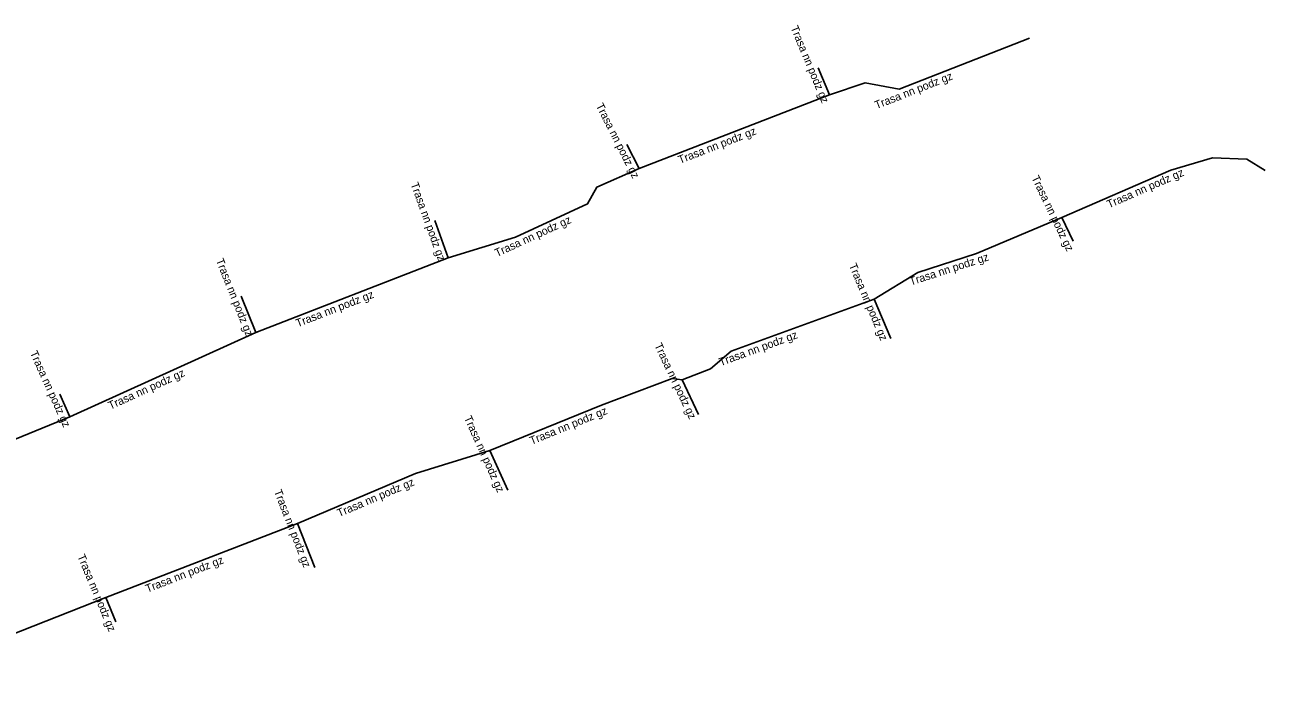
# Model space of a CAD drawing. Extents: x -467803 to -467116, y -1117596 to -1116713.
# Drawn here: x -467305.8 to -467228.3, y -1117118.8 to -1117076.7 of the extents above; entities that cross this region are included whole.
import ezdxf

# ---------------------------------------------------------------- set-up
doc = ezdxf.new("R2010")
doc.units = 0
doc.layers.add('Popiskový text - Ostatní atributy Trasy', color=7, linetype='Continuous')
doc.layers.add('Spojnice NN', color=7, linetype='Continuous')

msp = doc.modelspace()

# ---------------------------------------------------------------- linework, layer by layer
at = {"layer": 'Spojnice NN'}
for points in [[(-467255.53, -1117081.06), (-467253.29, -1117080.32), (-467251.17, -1117080.71), (-467243.03, -1117077.52)], [(-467255.53, -1117081.06), (-467256.23, -1117079.37)], [(-467267.43, -1117085.68), (-467255.53, -1117081.06)], [(-467267.43, -1117085.68), (-467268.19, -1117084.17)], [(-467228.297, -1117085.804), (-467229.435, -1117085.098), (-467231.59, -1117085.01), (-467234.2, -1117085.77), (-467241, -1117088.74)], [(-467279.36, -1117091.25), (-467275.15, -1117089.96), (-467270.65, -1117087.89), (-467270.07, -1117086.84), (-467267.43, -1117085.68)], [(-467279.36, -1117091.25), (-467280.2, -1117088.92)], [(-467241, -1117088.74), (-467246.34, -1117090.98), (-467250.01, -1117092.17), (-467252.73, -1117093.84)], [(-467241, -1117088.74), (-467240.29, -1117090.22)], [(-467291.39, -1117095.92), (-467279.36, -1117091.25)], [(-467291.39, -1117095.92), (-467292.29, -1117093.66)], [(-467252.73, -1117093.84), (-467261.67, -1117097.1), (-467262.96, -1117098.2), (-467264.74, -1117098.89)], [(-467252.73, -1117093.84), (-467251.7, -1117096.29)], [(-467303, -1117101.19), (-467291.39, -1117095.92)], [(-467264.74, -1117098.89), (-467265.37, -1117098.81), (-467269.77, -1117100.46), (-467276.75, -1117103.31)], [(-467264.74, -1117098.89), (-467263.72, -1117101.05)], [(-467303, -1117101.19), (-467303.64, -1117099.77)], [(-467314.67, -1117105.96), (-467303, -1117101.19)], [(-467276.75, -1117103.31), (-467281.4, -1117104.74), (-467288.77, -1117107.87)], [(-467276.75, -1117103.31), (-467275.64, -1117105.79)], [(-467288.77, -1117107.87), (-467300.76, -1117112.5)], [(-467288.77, -1117107.87), (-467287.7, -1117110.62)], [(-467300.76, -1117112.5), (-467312.93, -1117117.28), (-467312.407, -1117118.787)], [(-467300.76, -1117112.5), (-467300.13, -1117114.01)]]:
    msp.add_lwpolyline(points, dxfattribs=at)

# ---------------------------------------------------------------- texts
at = {"layer": 'Popiskový text - Ostatní atributy Trasy'}
for rotation, p in [(292.49939, (-467257.971, -1117076.866)), (21.39981, (-467252.59, -1117081.964)), (296.71663, (-467270.141, -1117081.739)), (21.21797, (-467264.874, -1117085.385)), (23.59401, (-467238.061, -1117088.166)), (289.825, (-467281.712, -1117086.643)), (295.62842, (-467242.916, -1117086.251)), (24.70243, (-467276.311, -1117091.209)), (291.71394, (-467293.885, -1117091.413)), (17.96532, (-467250.442, -1117092.994)), (292.80228, (-467254.323, -1117091.727)), (21.21602, (-467288.769, -1117095.6)), (20.03455, (-467262.328, -1117098.032)), (295.27772, (-467266.481, -1117096.727)), (294.26129, (-467305.513, -1117097.197)), (24.4142, (-467300.472, -1117100.756)), (294.11237, (-467278.379, -1117101.261)), (22.21066, (-467274.15, -1117102.95)), (23.01067, (-467286.176, -1117107.474)), (291.26056, (-467290.253, -1117105.852)), (292.6468, (-467302.544, -1117109.912)), (21.11432, (-467298.163, -1117112.194))]:
    msp.add_text('Trasa nn podz gz', height=0.5, rotation=rotation, dxfattribs=at).set_placement(p)

doc.saveas('drawing.dxf')
